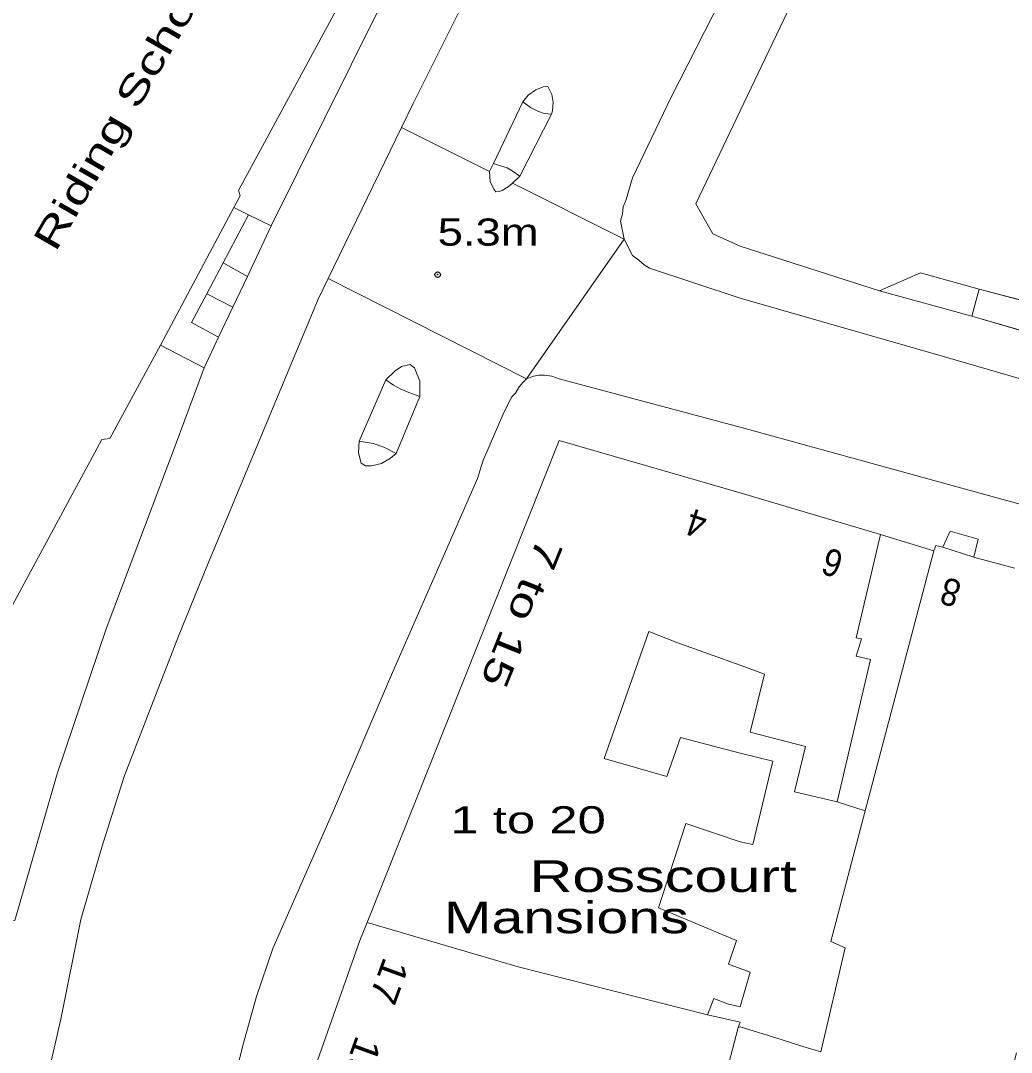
# Model space of a CAD drawing. Extents: x 528790 to 529292, y 179350 to 179856.
# Drawn here: x 528960.3 to 529015, y 179394.4 to 179451.4 of the extents above; entities that cross this region are included whole.
import ezdxf

# ---------------------------------------------------------------- set-up
doc = ezdxf.new("R2010")
doc.units = 0
doc.header["$LTSCALE"] = 0.6
doc.header["$PDMODE"] = 32
doc.header["$PDSIZE"] = 0.3
doc.layers.add('1', color=7, linetype='Continuous', lineweight=13)
doc.layers.add('2', color=7, linetype='Continuous', lineweight=13)
doc.layers.add('3', color=7, linetype='Continuous')
doc.layers.add('5', color=7, linetype='Continuous')

msp = doc.modelspace()

# ---------------------------------------------------------------- linework, layer by layer
at = {"layer": '1'}
for points in [[(529003.6, 179453.95), (529000, 179446.4), (528997.55, 179441.25), (528998.5, 179439.6), (529000, 179438.93), (529007.7, 179436.45), (529009.95, 179437.45), (529013.2, 179436.55), (529016.8, 179435.6), (529020.55, 179434.6), (529022.05, 179432.5), (529025.25, 179431.55), (529035.55, 179428.6), (529037.75, 179427.95), (529046, 179425.55), (529053.8, 179423.3), (529054.8, 179423.7), (529057.4, 179423.1), (529057.15, 179421.95), (529068.6, 179417.95), (529086.15, 179468.75)], [(528953.5, 179407.4), (528964.75, 179428.25), (528965.2, 179428.3), (528968, 179433.45), (528972.05, 179441.05), (528972.4, 179441.7), (528972.3, 179442), (528983.7, 179463.05)], [(528960.15, 179386.7), (528961, 179389.9), (528961.75, 179393.05), (528962.5, 179396.25), (528963.6, 179401.75), (528964.75, 179405.75), (528966, 179409.65), (528967.5, 179413.55), (528969, 179417.4), (528970.55, 179421.25), (528976.7, 179436), (528977.25, 179437.14), (528981.31, 179445.48), (528981.95, 179446.8), (528987.2, 179457.3)], [(528987.2, 179457.3), (528981.95, 179446.8), (528981.31, 179445.48), (528986.171, 179443.035), (528986.389, 179443.476), (528988.006, 179446.887), (528988.295, 179447.25), (528988.718, 179447.548), (528989.126, 179447.725), (528989.379, 179447.726), (528989.598, 179447.292), (528989.673, 179446.857), (528989.632, 179446.398), (528989.581, 179446.203), (528987.841, 179442.793), (528987.436, 179442.399), (528993.6, 179439.3), (528993.4, 179440.3), (528993.5, 179440.7), (528993.55, 179441.1), (528993.7, 179441.5), (528994.05, 179442.7), (528996.2, 179447.15), (528999.866, 179454.369)], [(528999.866, 179454.369), (528996.2, 179447.15), (528994.05, 179442.7), (528993.7, 179441.5), (528993.55, 179441.1), (528993.5, 179440.7), (528993.4, 179440.3), (528993.6, 179439.3), (528994.05, 179438.4), (528994.4, 179438.15), (528994.7, 179437.9), (528995, 179437.7), (529000, 179436.05), (529011.35, 179432.8), (529024.8, 179428.9)], [(529016.25, 179434.05), (529012.8, 179435.05), (529007.7, 179436.45), (529000, 179438.93), (528998.5, 179439.6), (528997.55, 179441.25), (529000, 179446.4), (529003.6, 179453.95)], [(528980, 179451.9), (528974.1, 179440.05), (528972.8, 179437.25), (528972, 179435.55), (528971.2, 179433.9), (528970.4, 179432.2), (528968.8, 179427.9), (528965, 179417.8), (528962.3, 179409.8), (528959.95, 179401.7)], [(528970.75, 179387.55), (528972.55, 179394.8), (528973.3, 179397.5), (528974.2, 179400.15), (528977.5, 179407.65), (528980.8, 179415.4), (528985.5, 179426.1), (528985.8, 179427.05), (528986.55, 179428.8), (528986.95, 179429.75), (528987.4, 179430.6), (528987.6, 179430.8), (528987.8, 179431.15), (528988, 179431.4), (528988.2, 179431.6), (528977.25, 179437.14), (528976.7, 179436), (528970.55, 179421.25), (528969, 179417.4), (528967.5, 179413.55), (528966, 179409.65), (528964.75, 179405.75), (528963.6, 179401.75), (528962.5, 179396.25), (528961.75, 179393.05)], [(529023, 179422.6), (529000, 179428.93), (528990, 179431.6), (528989.6, 179431.75), (528989.2, 179431.8), (528988.9, 179431.8), (528988.6, 179431.75), (528988.2, 179431.6), (528988, 179431.4), (528987.8, 179431.15), (528987.6, 179430.8), (528987.4, 179430.6), (528986.95, 179429.75), (528986.55, 179428.8), (528985.8, 179427.05), (528985.5, 179426.1), (528980.8, 179415.4), (528977.5, 179407.65), (528974.2, 179400.15), (528973.3, 179397.5), (528972.55, 179394.8), (528970.75, 179387.55)], [(528965.516, 179356.024), (528965.75, 179356.7), (528966.4, 179358.55), (528967.35, 179361.3), (528968.8, 179365.55), (528969.1, 179366.5), (528970.7, 179372.3), (528972.6, 179379.25), (528972.8, 179380.1), (528974.35, 179386.15), (528975.5, 179390.55), (528975.65, 179391.1), (528979, 179400.6), (528979.4, 179401.6), (528990, 179428.2), (529000, 179425.3), (529007.75, 179423), (529010.7, 179422.1), (529010.8, 179422.4), (529011.2, 179422.3), (529011.6, 179423.2), (529013.15, 179422.75), (529012.9, 179421.75), (529015.15, 179421.15)], [(529015.15, 179421.15), (529012.9, 179421.75), (529011.2, 179422.3), (529010.8, 179422.4), (529010.7, 179422.1), (529006.9, 179407.75), (529005, 179400.55), (529005.8, 179400.2), (529004.45, 179394.45), (529003.47, 179394.75), (529002.26, 179395.13), (529000, 179395.83), (528999.9, 179395.8), (528998.4, 179390.1), (528997.8, 179387.35), (529000, 179386.93), (529000.15, 179386.9), (529011.7, 179384.75), (529012.8, 179384.55), (529013.95, 179389.35), (529014.2, 179390.3), (529014.95, 179393.2), (529015.25, 179394.4)]]:
    msp.add_lwpolyline(points, dxfattribs=at)
for points in [[(528980, 179451.9), (528985.2, 179461.55), (528987.1, 179464.8), (528988.1, 179466.5), (528985.4, 179468), (528984.45, 179466.3), (528982.9, 179463.5), (528983.7, 179463.05), (528972.3, 179442), (528972.4, 179441.7), (528972.05, 179441.05), (528972.85, 179440.65), (528974.1, 179440.05)], [(528989.632, 179446.398), (528989.673, 179446.857), (528989.598, 179447.292), (528989.379, 179447.726), (528989.126, 179447.725), (528988.718, 179447.548), (528988.295, 179447.25), (528988.006, 179446.887), (528988.424, 179446.583), (528988.859, 179446.354), (528989.185, 179446.246), (528989.581, 179446.203)], [(528989.581, 179446.203), (528989.185, 179446.246), (528988.859, 179446.354), (528988.424, 179446.583), (528988.006, 179446.887), (528986.389, 179443.476), (528986.709, 179443.375), (528987.13, 179443.241), (528987.416, 179443.079), (528987.841, 179442.793)], [(528986.394, 179442.063), (528986.197, 179442.49), (528986.171, 179443.035), (528981.31, 179445.48), (528977.25, 179437.14), (528988.2, 179431.6), (528993.6, 179439.3), (528987.436, 179442.399), (528987.414, 179442.378), (528987.187, 179442.191), (528986.866, 179441.992), (528986.704, 179441.94), (528986.504, 179441.919)], [(528987.436, 179442.399), (528987.841, 179442.793), (528987.416, 179443.079), (528987.13, 179443.241), (528986.709, 179443.375), (528986.389, 179443.476), (528986.171, 179443.035), (528986.197, 179442.49), (528986.394, 179442.063), (528986.504, 179441.919), (528986.704, 179441.94), (528986.866, 179441.992), (528987.187, 179442.191), (528987.414, 179442.378)], [(528968, 179433.45), (528970.4, 179432.2), (528971.2, 179433.9), (528969.7, 179434.7), (528970.55, 179436.3), (528971.45, 179438), (528972.85, 179440.65), (528972.05, 179441.05)], [(528972.8, 179437.25), (528974.1, 179440.05), (528972.85, 179440.65), (528971.45, 179438)], [(529025.83, 179428.61), (529024.8, 179428.9), (529011.35, 179432.8), (529000, 179436.05), (528995, 179437.7), (528994.7, 179437.9), (528994.4, 179438.15), (528994.05, 179438.4), (528993.6, 179439.3), (528988.2, 179431.6), (528988.6, 179431.75), (528988.9, 179431.8), (528989.2, 179431.8), (528989.6, 179431.75), (528990, 179431.6), (529000, 179428.93), (529023, 179422.6), (529023.4, 179422.3), (529023.6, 179422.05), (529023.9, 179421.7)], [(528972, 179435.55), (528972.8, 179437.25), (528971.45, 179438), (528970.55, 179436.3)], [(529007.7, 179436.45), (529012.8, 179435.05), (529013.2, 179436.55), (529009.95, 179437.45)], [(528970.55, 179436.3), (528969.7, 179434.7), (528971.2, 179433.9), (528972, 179435.55)], [(529016.25, 179434.05), (529016.8, 179435.6), (529013.2, 179436.55), (529012.8, 179435.05)], [(528959.95, 179401.7), (528962.3, 179409.8), (528965, 179417.8), (528968.8, 179427.9), (528970.4, 179432.2), (528968, 179433.45), (528965.2, 179428.3), (528964.75, 179428.25), (528953.5, 179407.4), (528952.4, 179408), (528950.6, 179404.7), (528954.091, 179402.78), (528954.6, 179402.5)], [(528979.071, 179426.938), (528978.937, 179427.519), (528978.962, 179428.155), (528980.434, 179431.545), (528980.962, 179432.05), (528981.305, 179432.289), (528981.781, 179432.396), (528982.02, 179432.211), (528982.313, 179431.471), (528982.315, 179430.625), (528981.001, 179427.472), (528980.694, 179427.223), (528980.193, 179426.931), (528979.654, 179426.807), (528979.31, 179426.806)], [(528982.313, 179431.471), (528982.02, 179432.211), (528981.781, 179432.396), (528981.305, 179432.289), (528980.962, 179432.05), (528980.434, 179431.545), (528980.866, 179431.243), (528981.265, 179431.027), (528981.7, 179430.847), (528982.315, 179430.625)], [(528982.315, 179430.625), (528981.7, 179430.847), (528981.265, 179431.027), (528980.866, 179431.243), (528980.434, 179431.545), (528978.962, 179428.155), (528979.735, 179428.036), (528980.333, 179427.821), (528981.001, 179427.472)], [(529007.75, 179423), (529000, 179425.3), (528990, 179428.2), (528979.4, 179401.6), (528987.75, 179399.15), (528998.2, 179396.5), (528998.55, 179397.4), (528999.3, 179397.1), (529000, 179396.93), (529000.55, 179398.85), (529000, 179399.05), (528999.35, 179399.3), (528999.8, 179400.6), (528995.5, 179402.4), (528997, 179407.05), (529000, 179406.05), (529000.7, 179405.9), (529001.8, 179410.5), (529000, 179410.93), (528996.7, 179411.8), (528995.95, 179409.65), (528992.5, 179410.65), (528994.95, 179417.65), (528996.5, 179417.05), (529000, 179415.8), (529001.35, 179415.3), (529000.55, 179412.1), (529003.6, 179411.3), (529003, 179408.8), (529005.35, 179408.25), (529007.2, 179416.1), (529006.4, 179416.3), (529006.7, 179417.25), (529006.4, 179417.3)], [(528981.001, 179427.472), (528980.333, 179427.821), (528979.735, 179428.036), (528978.962, 179428.155), (528978.937, 179427.519), (528979.071, 179426.938), (528979.31, 179426.806), (528979.654, 179426.807), (528980.193, 179426.931), (528980.694, 179427.223)], [(529012.9, 179421.75), (529013.15, 179422.75), (529011.6, 179423.2), (529011.2, 179422.3)], [(529010.7, 179422.1), (529007.75, 179423), (529006.4, 179417.3), (529006.7, 179417.25), (529006.4, 179416.3), (529007.2, 179416.1), (529005.35, 179408.25), (529006.9, 179407.75)], [(529005.35, 179408.25), (529003, 179408.8), (529003.6, 179411.3), (529000.55, 179412.1), (529001.35, 179415.3), (529000, 179415.8), (528996.5, 179417.05), (528994.95, 179417.65), (528992.5, 179410.65), (528995.95, 179409.65), (528996.7, 179411.8), (529000, 179410.93), (529001.8, 179410.5), (529000.7, 179405.9), (529000, 179406.05), (528997, 179407.05), (528995.5, 179402.4), (528999.8, 179400.6), (528999.35, 179399.3), (529000, 179399.05), (529000.55, 179398.85), (529000, 179396.93), (528999.3, 179397.1), (528998.55, 179397.4), (528998.2, 179396.5), (529000, 179396.1), (528999.9, 179395.8), (529000, 179395.83), (529002.26, 179395.13), (529003.47, 179394.75), (529004.45, 179394.45), (529005.8, 179400.2), (529005, 179400.55), (529006.9, 179407.75)], [(528998.2, 179396.5), (528987.75, 179399.15), (528979.4, 179401.6), (528979, 179400.6), (528975.65, 179391.1), (528986.15, 179389.2), (528986.55, 179389.9), (528994.2, 179388.15), (528997.05, 179387.5), (528997.8, 179387.35), (528998.4, 179390.1), (528999.9, 179395.8), (529000, 179396.1)]]:
    msp.add_lwpolyline(points, close=True, dxfattribs=at)
at = {"layer": '2'}
for p, q in [((528986.389, 179443.476), (528988.006, 179446.887)), ((528989.581, 179446.203), (528987.841, 179442.793)), ((528981.31, 179445.48), (528977.25, 179437.14)), ((528986.171, 179443.035), (528981.31, 179445.48)), ((528986.171, 179443.035), (528986.389, 179443.476)), ((528987.841, 179442.793), (528987.436, 179442.399)), ((528993.6, 179439.3), (528987.436, 179442.399)), ((528968, 179433.45), (528972.05, 179441.05)), ((528972.05, 179441.05), (528972.85, 179440.65)), ((528972.85, 179440.65), (528971.45, 179438)), ((528972.85, 179440.65), (528974.1, 179440.05)), ((528974.1, 179440.05), (528972.8, 179437.25)), ((528988.2, 179431.6), (528993.6, 179439.3)), ((528971.45, 179438), (528970.55, 179436.3)), ((528971.45, 179438), (528972.8, 179437.25)), ((528972.8, 179437.25), (528972, 179435.55)), ((528988.2, 179431.6), (528977.25, 179437.14)), ((528970.55, 179436.3), (528972, 179435.55)), ((529012.8, 179435.05), (529007.7, 179436.45)), ((529013.2, 179436.55), (529012.8, 179435.05)), ((529013.2, 179436.55), (529016.8, 179435.6)), ((528972, 179435.55), (528971.2, 179433.9)), ((529016.25, 179434.05), (529012.8, 179435.05)), ((528971.2, 179433.9), (528970.4, 179432.2)), ((528970.4, 179432.2), (528968, 179433.45)), ((528978.962, 179428.155), (528980.434, 179431.545)), ((528982.315, 179430.625), (528981.001, 179427.472)), ((529010.7, 179422.1), (529007.75, 179423)), ((529010.7, 179422.1), (529006.9, 179407.75)), ((529012.9, 179421.75), (529011.2, 179422.3)), ((529015.15, 179421.15), (529012.9, 179421.75)), ((529005.35, 179408.25), (529006.9, 179407.75))]:
    msp.add_line(p, q, dxfattribs=at)
for points in [[(528988.542, 179467.133), (528991.564, 179465.226), (528991.609, 179464.932), (528991.3, 179464.4), (528987.2, 179457.3), (528981.95, 179446.8), (528981.31, 179445.48)], [(528988.1, 179466.5), (528987.1, 179464.8), (528985.2, 179461.55), (528980, 179451.9), (528974.1, 179440.05)], [(528972.05, 179441.05), (528972.4, 179441.7), (528972.3, 179442), (528983.7, 179463.05), (528982.9, 179463.5), (528984.45, 179466.3)], [(528993.6, 179439.3), (528993.4, 179440.3), (528993.5, 179440.7), (528993.55, 179441.1), (528993.7, 179441.5), (528994.05, 179442.7), (528996.2, 179447.15), (528999.866, 179454.369)], [(529003.6, 179453.95), (529000, 179446.4), (528997.55, 179441.25), (528998.5, 179439.6), (529000, 179438.93), (529007.7, 179436.45)], [(528988.006, 179446.887), (528988.295, 179447.25), (528988.718, 179447.548), (528989.126, 179447.725), (528989.379, 179447.726), (528989.598, 179447.292), (528989.673, 179446.857), (528989.632, 179446.398), (528989.581, 179446.203)], [(528988.006, 179446.887), (528988.424, 179446.583), (528988.859, 179446.354), (528989.185, 179446.246), (528989.581, 179446.203)], [(528987.436, 179442.399), (528987.414, 179442.378), (528987.187, 179442.191), (528986.866, 179441.992), (528986.704, 179441.94), (528986.504, 179441.919), (528986.394, 179442.063), (528986.197, 179442.49), (528986.171, 179443.035)], [(528986.389, 179443.476), (528986.709, 179443.375), (528987.13, 179443.241), (528987.416, 179443.079), (528987.841, 179442.793)], [(528993.6, 179439.3), (528994.05, 179438.4), (528994.4, 179438.15), (528994.7, 179437.9), (528995, 179437.7), (529000, 179436.05), (529011.35, 179432.8), (529024.8, 179428.9), (529025.83, 179428.61)], [(529007.7, 179436.45), (529009.95, 179437.45), (529013.2, 179436.55)], [(528977.25, 179437.14), (528976.7, 179436), (528970.55, 179421.25), (528969, 179417.4), (528967.5, 179413.55), (528966, 179409.65), (528964.75, 179405.75), (528963.6, 179401.75), (528962.5, 179396.25), (528961.75, 179393.05), (528961, 179389.9), (528960.15, 179386.7)], [(528970.55, 179436.3), (528969.7, 179434.7), (528971.2, 179433.9)], [(528952.4, 179408), (528953.5, 179407.4), (528964.75, 179428.25), (528965.2, 179428.3), (528968, 179433.45)], [(528970.4, 179432.2), (528968.8, 179427.9), (528965, 179417.8), (528962.3, 179409.8), (528959.95, 179401.7)], [(528980.434, 179431.545), (528980.962, 179432.05), (528981.305, 179432.289), (528981.781, 179432.396), (528982.02, 179432.211), (528982.313, 179431.471), (528982.315, 179430.625)], [(528988.2, 179431.6), (528988.6, 179431.75), (528988.9, 179431.8), (528989.2, 179431.8), (528989.6, 179431.75), (528990, 179431.6), (529000, 179428.93), (529023, 179422.6), (529023.4, 179422.3), (529023.6, 179422.05), (529023.9, 179421.7)], [(528961.131, 179356.024), (528964, 179364.05), (528966.6, 179372.15), (528969, 179380.3), (528970.75, 179387.55), (528972.55, 179394.8), (528973.3, 179397.5), (528974.2, 179400.15), (528977.5, 179407.65), (528980.8, 179415.4), (528985.5, 179426.1), (528985.8, 179427.05), (528986.55, 179428.8), (528986.95, 179429.75), (528987.4, 179430.6), (528987.6, 179430.8), (528987.8, 179431.15), (528988, 179431.4), (528988.2, 179431.6)], [(528980.434, 179431.545), (528980.866, 179431.243), (528981.265, 179431.027), (528981.7, 179430.847), (528982.315, 179430.625)], [(529007.75, 179423), (529000, 179425.3), (528990, 179428.2), (528979.4, 179401.6)], [(528981.001, 179427.472), (528980.694, 179427.223), (528980.193, 179426.931), (528979.654, 179426.807), (528979.31, 179426.806), (528979.071, 179426.938), (528978.937, 179427.519), (528978.962, 179428.155)], [(528978.962, 179428.155), (528979.735, 179428.036), (528980.333, 179427.821), (528981.001, 179427.472)], [(529011.2, 179422.3), (529011.6, 179423.2), (529013.15, 179422.75), (529012.9, 179421.75)], [(529005.35, 179408.25), (529007.2, 179416.1), (529006.4, 179416.3), (529006.7, 179417.25), (529006.4, 179417.3), (529007.75, 179423)], [(529011.2, 179422.3), (529010.8, 179422.4), (529010.7, 179422.1)], [(529005.35, 179408.25), (529003, 179408.8), (529003.6, 179411.3), (529000.55, 179412.1), (529001.35, 179415.3), (529000, 179415.8), (528996.5, 179417.05), (528994.95, 179417.65), (528992.5, 179410.65), (528995.95, 179409.65), (528996.7, 179411.8), (529000, 179410.93), (529001.8, 179410.5), (529000.7, 179405.9), (529000, 179406.05), (528997, 179407.05), (528995.5, 179402.4), (528999.8, 179400.6), (528999.35, 179399.3), (529000, 179399.05), (529000.55, 179398.85), (529000, 179396.93), (528999.3, 179397.1), (528998.55, 179397.4), (528998.2, 179396.5)], [(528999.9, 179395.8), (529000, 179395.83), (529002.26, 179395.13), (529003.47, 179394.75), (529004.45, 179394.45), (529005.8, 179400.2), (529005, 179400.55), (529006.9, 179407.75)], [(528979.4, 179401.6), (528979, 179400.6), (528975.65, 179391.1)], [(528998.2, 179396.5), (528987.75, 179399.15), (528979.4, 179401.6)], [(528999.9, 179395.8), (529000, 179396.1), (528998.2, 179396.5)], [(528997.8, 179387.35), (528998.4, 179390.1), (528999.9, 179395.8)]]:
    msp.add_lwpolyline(points, dxfattribs=at)
at = {"layer": '3'}
msp.add_point((528983.3, 179437.35), dxfattribs=at)

# ---------------------------------------------------------------- texts
at = {"layer": '5'}
for s, rotation, width, p in [('Riding School', 60, 1.45, (528962.2, 179438.55)), ('4', 162, 0.9, (528998.29, 179424.17)), ('7 to 15', 248, 1.4, (528988.86, 179422.92)), ('6', 162, 0.9, (529005.8, 179422)), ('8', 164, 0.9, (529012.3, 179420.4)), ('17', 250, 1.1, (528980.34, 179399.75)), ('19', 250, 1.1, (528978.82, 179395.42))]:
    msp.add_text(s, height=1.5, rotation=rotation, dxfattribs=dict(at, width=width)).set_placement(p)
for s, height, width, p in [('5.3m', 1.5, 1.25, (528983.3, 179438.95)), ('1 to 20', 1.5, 1.4, (528984, 179406.51)), ('Rosscourt', 1.75, 1.4, (528988.37, 179403.28)), ('Mansions', 1.75, 1.35, (528983.64, 179401))]:
    msp.add_text(s, height=height, dxfattribs=dict(at, width=width)).set_placement(p)

doc.saveas('drawing.dxf')
